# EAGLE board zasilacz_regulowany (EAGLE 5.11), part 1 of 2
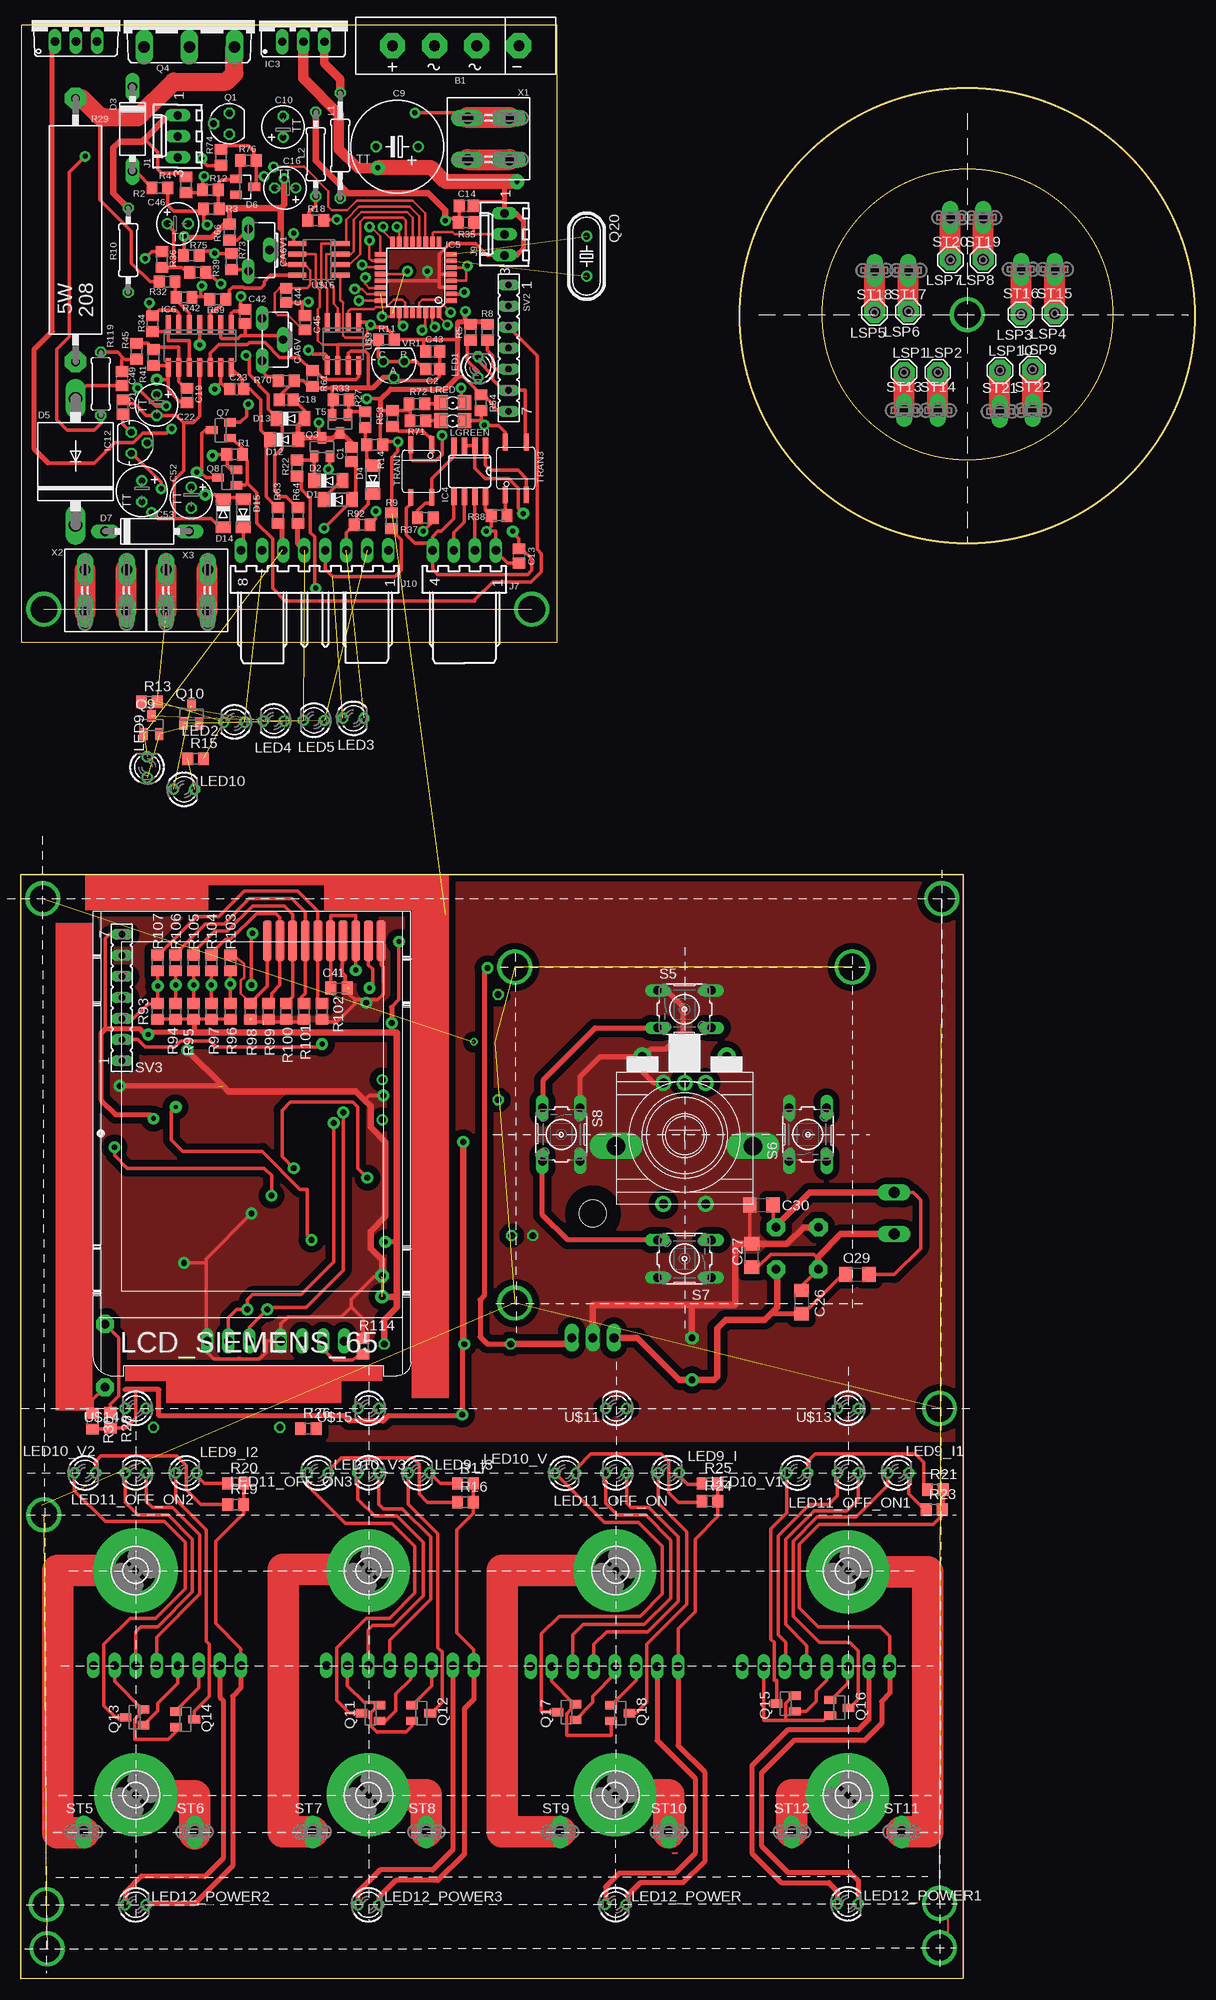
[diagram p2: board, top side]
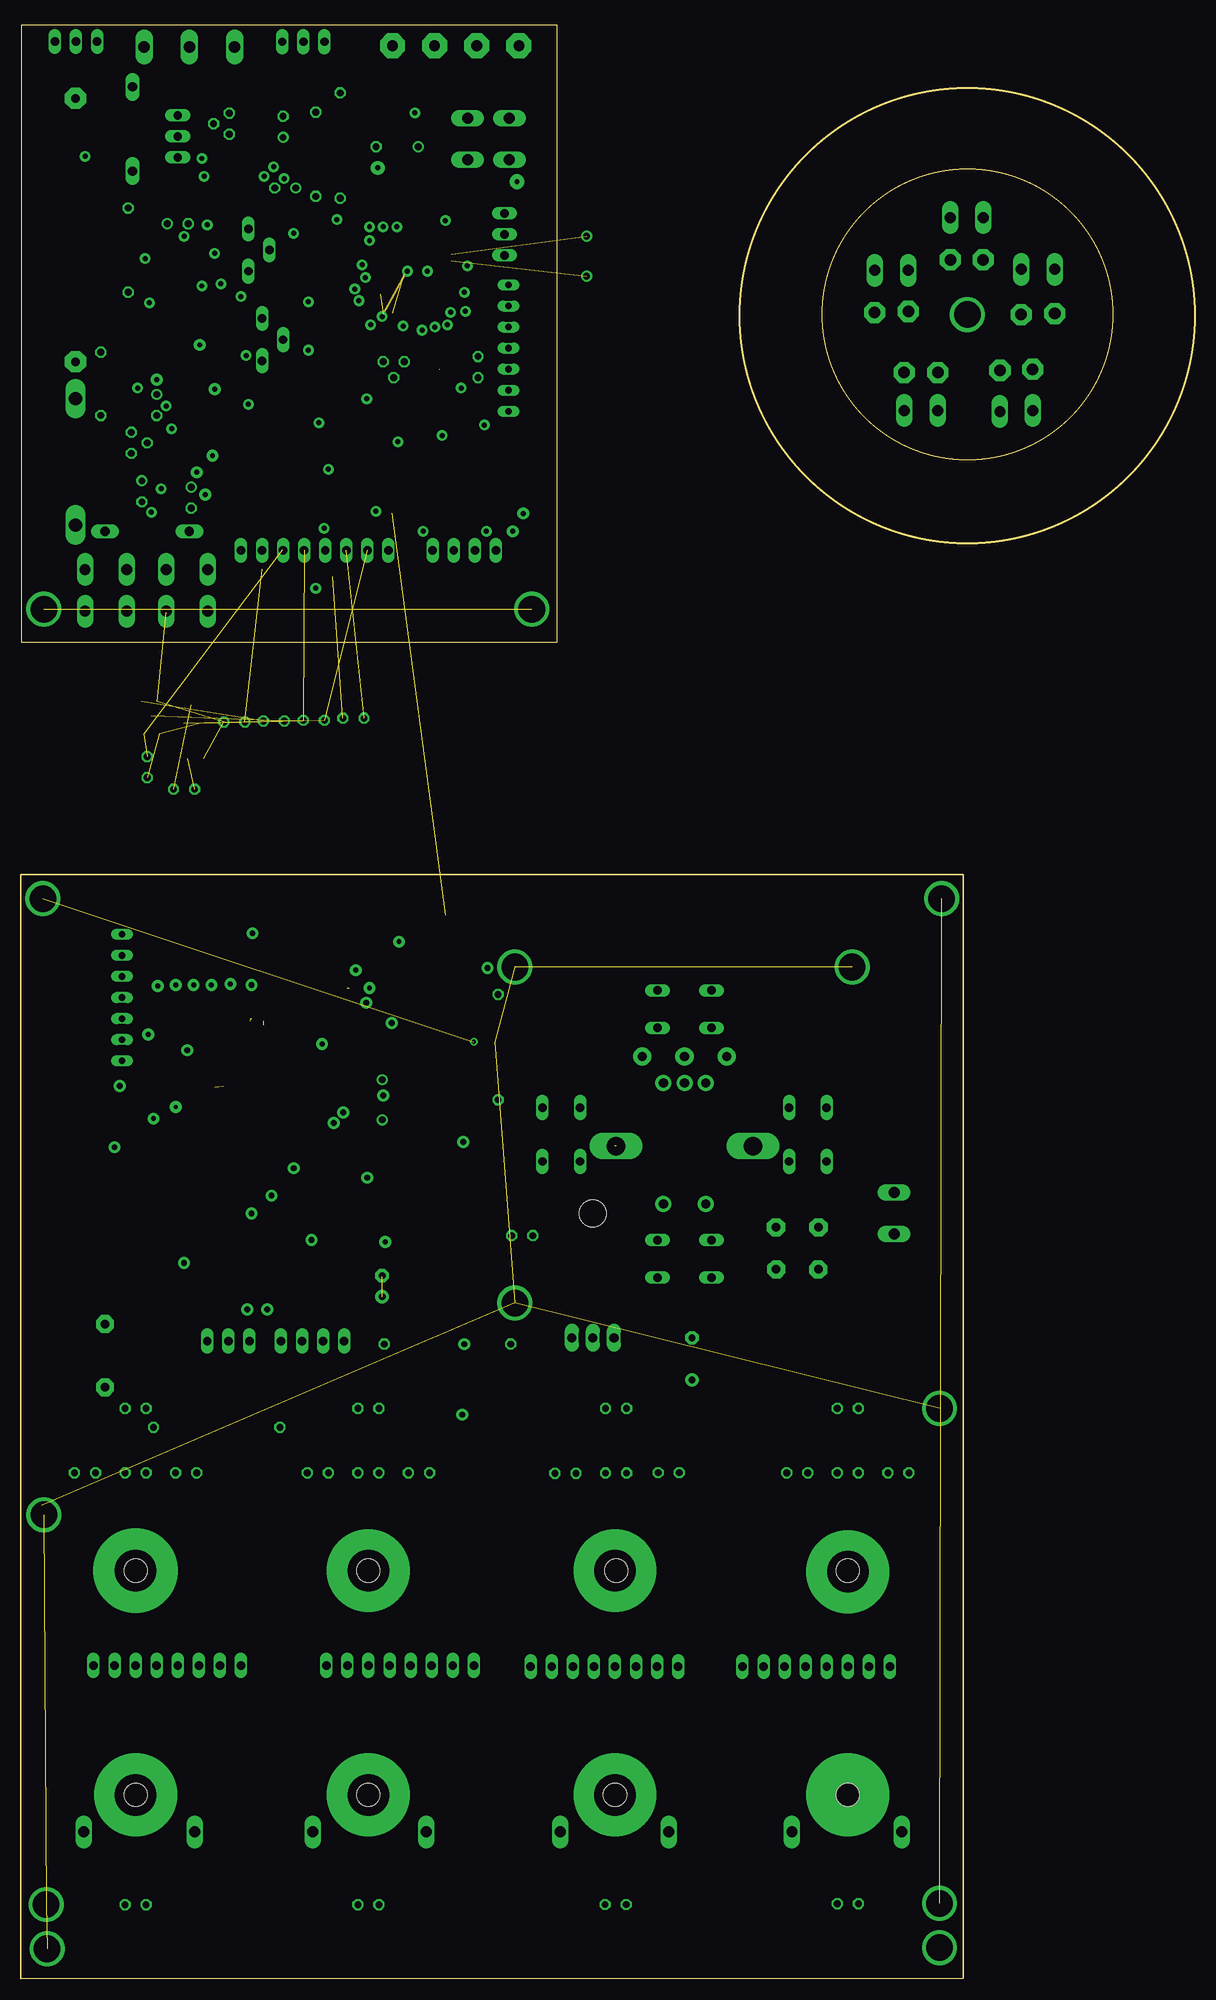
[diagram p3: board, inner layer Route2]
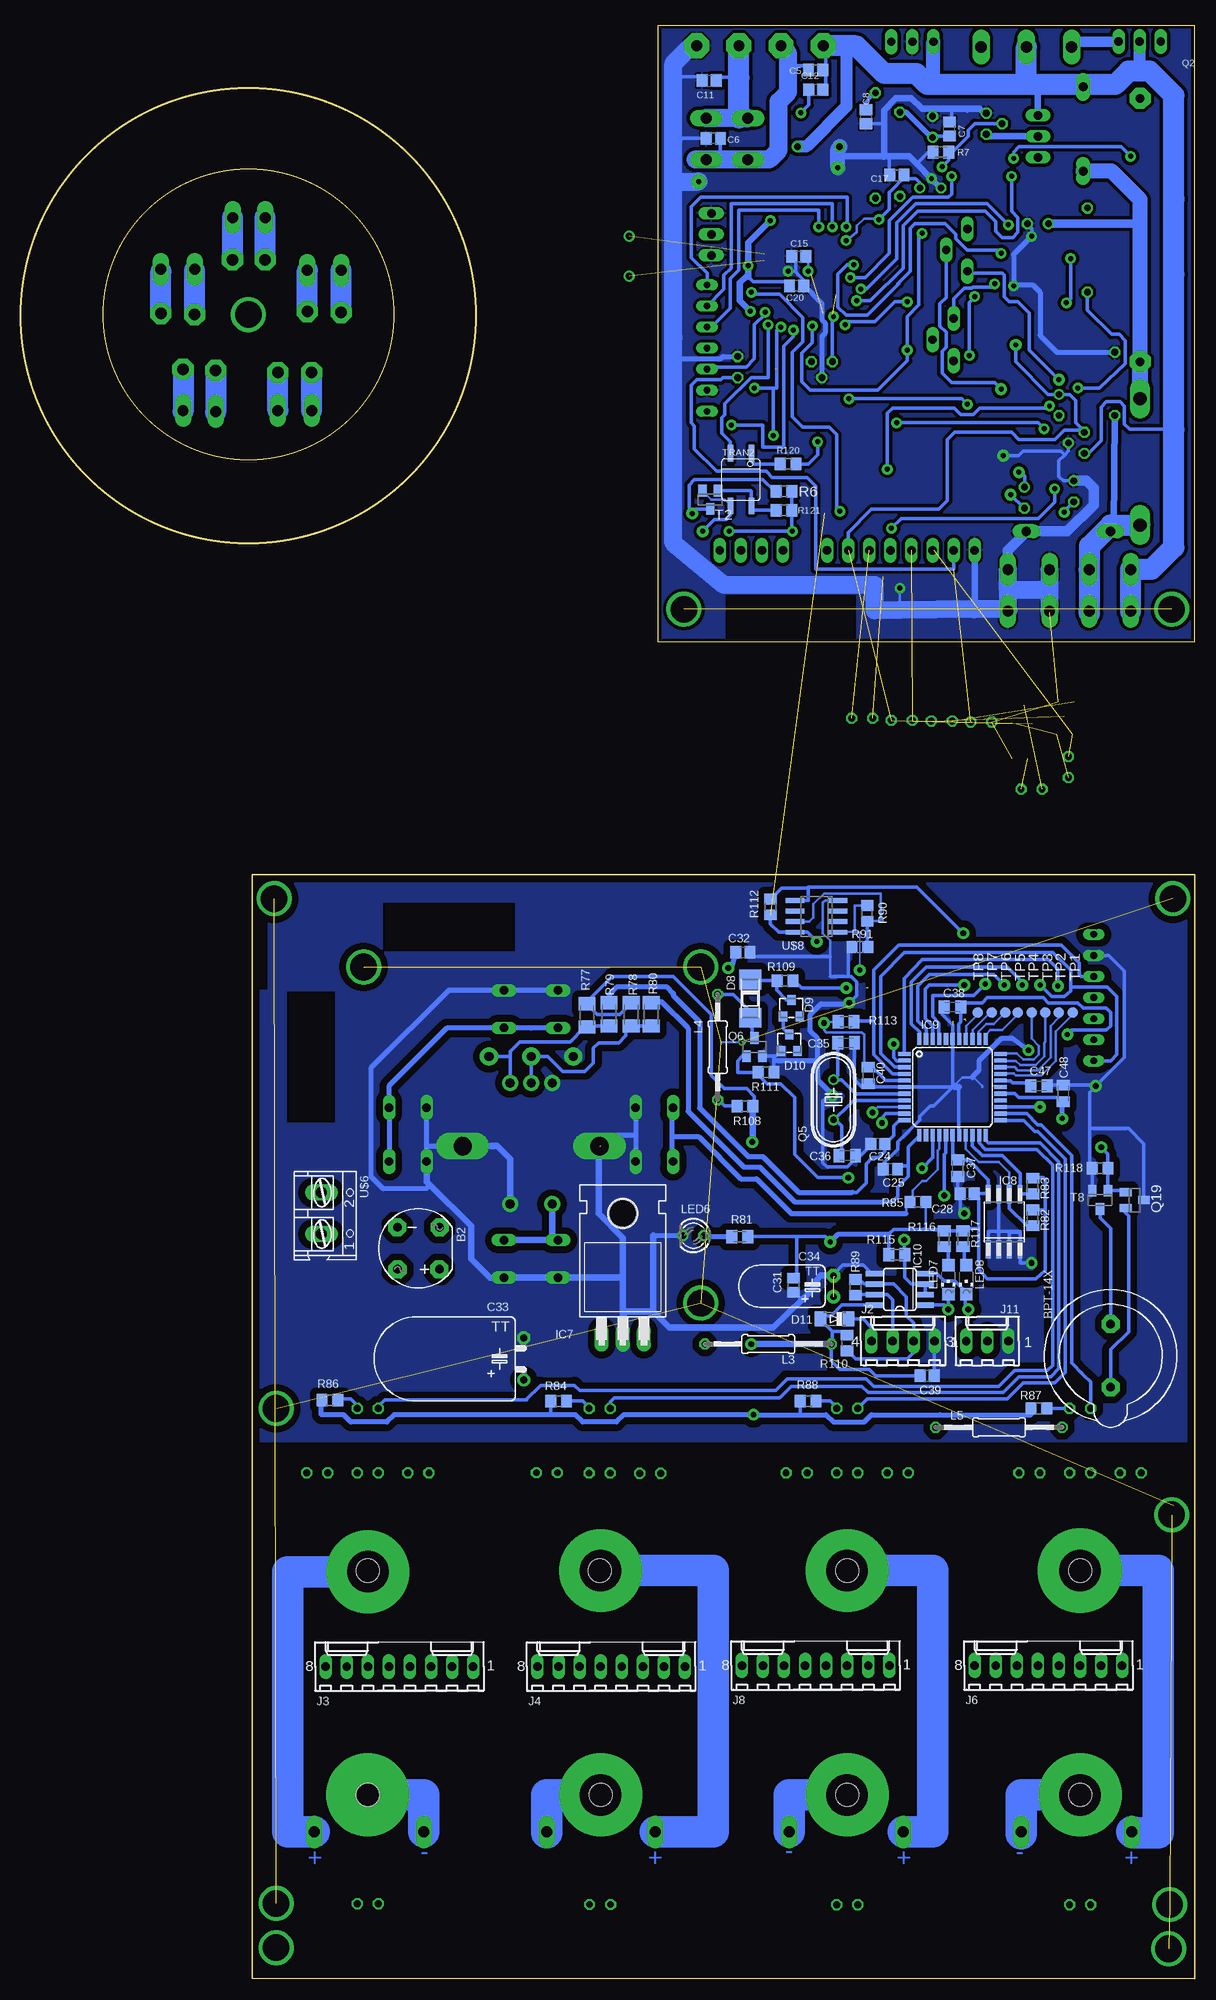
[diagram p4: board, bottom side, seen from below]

Size 141.52 x 235.56 mm. Coordinates in mm from the lower left corner, seen from the top.
Outline: 0.05,161.14 64.67,161.14 64.67,235.56 0.05,235.56 0.05,161.14
Outline: 0,0 113.61,0.05 113.61,133.12 0,133.15 0,0
Outline: circle at 114.09,200.65 radius 17.53
Outline: circle at 114.09,200.52 radius 27.43
Copper layers (1*16): Top 0.035mm / dielectric 1.5mm / Bottom 0.035mm
Design rules "default": minimum track width 10mil, minimum drill 20mil, track to track 8mil, track to pad 8mil, pad to pad 8mil, via to via 8mil, smd to smd 8mil, copper to edge 1mil, drill to drill 8mil, minimum pad ring 10mil, minimum via ring 8mil, stop-mask expansion 4mil, vias tented up to drill 0mil, thermal gap 10mil

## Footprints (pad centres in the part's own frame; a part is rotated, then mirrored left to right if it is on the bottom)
2KBB_R2 = drill 1.3 pad 3 octagon: + -7.62,0; - 7.62,0; ~1 -2.54,0; ~2 2.54,0
RB1A = drill 1.016 round: + -2.54,2.54 | drill 1.016 octagon: - 2.54,-2.54; AC1 2.54,2.54; AC2 -2.54,-2.54
F/HGP = drill 1.016 pad 2.159 octagon: 1 -3.81,0; 2 3.81,0
C0805 = smd 1.3 x 1.5: 1 -0.85,0; 2 0.85,0
TT5D11 = drill 0.813 round: + -2.54,0 | drill 0.813 octagon: - 2.54,0
TT2D5 = drill 0.813 round: + -1.27,0 | drill 0.813 octagon: - 1.27,0
C1206 = smd 1.6 x 1.8: 1 -1.4,0; 2 1.4,0
TT5D11L = drill 0.813 pad 1.6 round: + -2.54,0 | drill 0.813 pad 1.6 octagon: - 2.54,0
TT2D5L = drill 0.813 pad 1.6 round: + -1.27,0 | drill 0.813 pad 1.6 octagon: - 1.27,0
C0805K = smd 1.3 x 1.6: 1 -1,0; 2 1,0
TT2D6 = drill 0.813 round: + -1.27,0 | drill 0.813 octagon: - 1.27,0
CA6H = drill 1.016 long: A -2.54,0; E 2.54,0; S 0,2.54
MINIMELF = smd 1.4 x 1.8: A 1.7,0; C -1.7,0
P1-10 = drill 1.118 long: A 5.08,0; C -5.08,0
P6-15 = drill 1.6 long: A 7.62,0; C -7.62,0
SOT23 = smd 1 x 1.4: 1 -0.95,-1.1; 2 0.95,-1.1; 3 0,1.1
SOD106A = smd 2.4 x 2.6: A 2.3,0; K -2.3,0
TO236 = smd 1 x 1.2: A -1,-1; C 0,1; NC 1,-1
2,8 = hole 2.8: 0,0
78XXS = drill 1.016 long: GND 0,-2.54; IN -2.54,-2.54; OUT 2.54,-2.54
SO08 = smd 0.66 x 2.032: 1 -1.905,-3.073; 2 -0.635,-3.073; 3 0.635,-3.073; 4 1.905,-3.073; 5 1.905,3.073; 6 0.635,3.073; 7 -0.635,3.073; 8 -1.905,3.073
TQFP32-08 = smd 1.27 x 0.559: 1 -4.293,2.8; 2 -4.293,2; 3 -4.293,1.2; 4 -4.293,0.4; 5 -4.293,-0.4; 6 -4.293,-1.2; 7 -4.293,-2; 8 -4.293,-2.8; 17 4.293,-2.8; 18 4.293,-2; 19 4.293,-1.2; 20 4.293,-0.4; 21 4.293,0.4; 22 4.293,1.2; 23 4.293,2; 24 4.293,2.8 | smd 0.559 x 1.27: 9 -2.8,-4.293; 10 -2,-4.293; 11 -1.2,-4.293; 12 -0.4,-4.293; 13 0.4,-4.293; 14 1.2,-4.293; 15 2,-4.293; 16 2.8,-4.293; 25 2.8,4.293; 26 2,4.293; 27 1.2,4.293; 28 0.4,4.293; 29 -0.4,4.293; 30 -1.2,4.293; 31 -2,4.293; 32 -2.8,4.293
SO14 = smd 0.6 x 2.2: 1 -3.81,-2.6; 2 -2.54,-2.6; 3 -1.27,-2.6; 4 0,-2.6; 5 1.27,-2.6; 6 2.54,-2.6; 7 3.81,-2.6; 8 3.81,2.6; 9 2.54,2.6; 10 1.27,2.6; 11 0,2.6; 12 -1.27,2.6; 13 -2.54,2.6; 14 -3.81,2.6
TO220H = drill 1.118 long: 1 -2.54,-10.16; 2 0,-10.16; 3 2.54,-10.16 | hole 3.302: 0,4.826
SO-08M = smd 0.6 x 2.2: 1 -1.905,-3.33; 2 -0.635,-3.33; 3 0.635,-3.33; 4 1.905,-3.33; 5 1.905,3.33; 6 0.635,3.33; 7 -0.635,3.33; 8 -1.905,3.33
TQFP44 = smd 1.5 x 0.5: 1 -5.8,4; 2 -5.8,3.2; 3 -5.8,2.4; 4 -5.8,1.6; 5 -5.8,0.8; 6 -5.8,0; 7 -5.8,-0.8; 8 -5.8,-1.6; 9 -5.8,-2.4; 10 -5.8,-3.2; 11 -5.8,-4; 23 5.8,-4; 24 5.8,-3.2; 25 5.8,-2.4; 26 5.8,-1.6; 27 5.8,-0.8; 28 5.8,0; 29 5.8,0.8; 30 5.8,1.6; 31 5.8,2.4; 32 5.8,3.2; 33 5.8,4 | smd 0.5 x 1.5: 12 -4,-5.8; 13 -3.2,-5.8; 14 -2.4,-5.8; 15 -1.6,-5.8; 16 -0.8,-5.8; 17 0,-5.8; 18 0.8,-5.8; 19 1.6,-5.8; 20 2.4,-5.8; 21 3.2,-5.8; 22 4,-5.8; 34 4,5.8; 35 3.2,5.8; 36 2.4,5.8; 37 1.6,5.8; 38 0.8,5.8; 39 0,5.8; 40 -0.8,5.8; 41 -1.6,5.8; 42 -2.4,5.8; 43 -3.2,5.8; 44 -4,5.8
78LXX = drill 0.813 octagon: GND 0,1.905; IN 1.27,0; OUT -1.27,0
6410-03 = drill 1.016 long: 1 2.54,0; 2 0,0; 3 -2.54,0
6410-04 = drill 1.016 long: 1 3.81,0; 2 1.27,0; 3 -1.27,0; 4 -3.81,0
6410-08 = drill 1.016 long: 1 8.89,0; 2 6.35,0; 3 3.81,0; 4 1.27,0; 5 -1.27,0; 6 -3.81,0; 7 -6.35,0; 8 -8.89,0
7395-04 = drill 1.016 long: 1 3.81,0; 2 1.27,0; 3 -1.27,0; 4 -3.81,0
7395-08 = drill 1.016 long: 1 8.89,0; 2 6.35,0; 3 3.81,0; 4 1.27,0; 5 -1.27,0; 6 -3.81,0; 7 -6.35,0; 8 -8.89,0
0207/12 = drill 0.813 octagon: 1 -6.35,0; 2 6.35,0
0207/10 = drill 0.813 octagon: 1 -5.08,0; 2 5.08,0
0207/15@1 = drill 0.813 octagon: 1 -7.62,0; 2 7.62,0
LED3MM = drill 0.813 octagon: A -1.27,0; K 1.27,0
CHIPLED_1206 = smd 1.5 x 1.5: A 0,-1.75; C 0,1.75
1206 = smd 1.6 x 1.803: A -1.422,0; C 1.422,0
SE14 = drill 1.397 pad 2.54 octagon: MP 0,0
SOT54E = drill 0.813 octagon: D -1.27,0; G 0,1.905; S 1.27,0
TO220AV = drill 1.016 long: B -2.54,-2.54; C 0,-2.54; E 2.54,-2.54
TOP3AV = drill 1.397 long: B -5.461,-3.175; C 0,-3.175; E 5.461,-3.175
HC49U70 = drill 0.813 round: 1 -2.413,0; 2 2.413,0
HC49/S = drill 0.813 round: 1 -2.413,0; 2 2.413,0
R0805 = smd 1.3 x 1.5: 1 -0.95,0; 2 0.95,0
M0805 = smd 1.3 x 1.6: 1 -0.95,0; 2 0.95,0
KH208-8 = drill 1.016 pad 2.54 octagon: 1 -15.875,0; 2 15.875,0
M1206 = smd 1.6 x 2: 1 -1.4,0; 2 1.4,0
0207/7 = drill 0.813 octagon: 1 -3.81,0; 2 3.81,0
B3F-10XX = drill 1.016 long: 1 -3.251,2.261; 2 3.251,2.261; 3 -3.251,-2.261; 4 3.251,-2.261
ST2,8 = drill 1.321 long: 1 0,0
FE07 = drill 0.813 long: 1 -7.62,0; 2 -5.08,0; 3 -2.54,0; 4 0,0; 5 2.54,0; 6 5.08,0; 7 7.62,0
B1,27 = smd 1.27 x 1.27: PP 0,0
MFP4 = smd 2.032 x 0.635: 1 -3.226,1.295; 2 -3.226,-1.245; 3 3.15,-1.245; 4 3.15,1.295
ENKODER_PROSTY = drill 1.1 pad 2.184 round: A -5.08,0; B 0,0; C 5.08,0 | drill 1.1 pad 1.93 round: A.A -2.54,3.175; B.B 0,3.175; C.C 2.54,3.175; S1 -2.54,17.78; S2 2.54,17.78 | drill 2.2 pad 3 long: GN -8.255,10.795; GN1 8.255,10.795
AK300/2_MK = drill 1.321 long: 1 -2.515,0; 2 2.489,0
SIEMENS65 = smd 5 x 1.1: 1V8 -21.463,11.938; 2V9 -21.463,8.89; CLK -21.463,5.842; CS -21.463,4.318; DAT -21.463,7.366; GND -21.463,10.414; LED+ -21.463,13.462; LED_GND -21.463,14.986; RESET -21.463,2.794; RS -21.463,1.27
SO08' = smd 0.6 x 2.2: 1 -1.905,-2.6; 2 -0.635,-2.6; 3 0.635,-2.6; 4 1.905,-2.6; 5 1.905,2.6; 6 0.635,2.6; 7 -0.635,2.6; 8 -1.905,2.6
SO-08 = smd 0.6 x 2.2: 1 -1.905,-2.6; 2 -0.635,-2.6; 3 0.635,-2.6; 4 1.905,-2.6; 5 1.905,2.6; 6 0.635,2.6; 7 -0.635,2.6; 8 -1.905,2.6
TO92-CLP = drill 0.813 octagon: A 0,1.905; C 1.27,0; R -1.27,0
SH5-2 = drill 1.321 long: 1 0,-2.515; 2 0,2.515; 3 5.004,-2.515; 4 5.004,2.515

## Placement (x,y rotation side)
B1  B600C8000  [2KBB_R2]  52.42,233.06 0 top
B2  B50C1500  [RB1A]  93.59,88.07 180 bottom
BPT-14X  BPT-14X  [F/HGP]  10.15,75.12 90 bottom
C1  10n  [C0805]  39.87,183.78 270 top
C2  1n  [C0805]  49.65,194.07 0 top
C5  100n  [C0805]  45.72,230.13 0 bottom
C6  100n  [C0805]  58.03,221.88 180 bottom
C7  100n  [C0805]  29.59,223.02 90 bottom
C8  100n  [C0805]  39.64,224.5 270 bottom
C9  1000u/25V  [TT5D11]  45.36,220.89 180 top
C10  100u  [TT2D5]  31.62,223.28 90 top
C11  100n  [C0805]  58.54,228.87 0 bottom
C12  100n  [C0805]  45.69,227.75 0 bottom
C13  100n  [C0805]  60.04,171.54 270 top
C14  100n  [C0805]  53.69,213.75 0 top
C15  1n  [C0805]  47.75,207.66 0 bottom
C16  4u7  [TT2D5]  31.87,215.91 180 top
C17  100n  [C0805]  35.91,217.46 0 bottom
C18  10n  [C0805]  32,190.38 180 top
C19  10n  [C0805]  20.06,190.89 90 top
C20  100n  [C0805]  48,204.1 180 bottom
C21  100n  [C0805]  12.31,189.5 90 top
C22  10u  [TT2D5]  16.38,189.75 270 top
C23  10n  [C0805]  26.03,191.65 0 top
C24  1n  [C0805]  38.22,100.65 180 bottom
C25  1n  [C0805]  36.7,97.6 180 bottom
C26  100n  [C1206]  94.1,81.6 270 top
C27  100n  [C1206]  88.13,87.21 90 top
C28  100n  [C0805]  27.43,94.68 180 bottom
C29  100n  [C1206]  100.83,84.9 0 top
C30  100n  [C1206]  89.28,93.28 0 top
C31  100n  [C0805]  48.38,83.63 270 bottom
C32  100n  [C0805]  54.48,123.76 0 bottom
C33  1000u/25V  [TT5D11L]  80.89,74.74 90 bottom
C34  100u  [TT2D5L]  43.56,83.5 90 bottom
C35  15p  [C0805K]  42.03,112.84 180 bottom
C36  15p  [C0805K]  41.91,99.25 180 bottom
C37  100n  [C0805K]  28.57,97.72 270 bottom
C38  100n  [C0805K]  29.2,117.16 0 bottom
C39  100n  [C0805]  32.25,72.71 180 bottom
C40  100n  [C0805K]  39.36,108.9 90 bottom
C41  100n  [C0805K]  38.35,119.44 180 top
C42  10n  [C0805]  27.05,200.42 270 top
C43  100n  [C0805]  49.65,196.23 0 top
C44  100n  [C0805]  32,202.96 270 top
C45  100n  [C0805]  34.28,199.65 270 top
C46  1u  [TT2D5]  18.92,211.59 0 top
C47  1n5  [C0805K]  18.79,107.63 0 bottom
C48  100n  [C0805K]  15.87,106.74 270 bottom
C49  100n  [C0805]  12.19,192.92 270 top
C52  22u  [TT2D5]  20.54,178.57 270 top
C53  100u  [TT2D6]  14.6,179.33 270 top
CA6V  1k  [CA6H]  29.08,197.62 270 top
CA6V1  1k  [CA6H]  27.43,208.42 270 top
D1  BAV103  [MINIMELF]  38.22,178.32 0 top
D2  BAV103  [MINIMELF]  37.08,180.6 0 top
D3  1N4002  [P1-10]  13.46,223.02 270 top
D4  [MINIMELF]  42.41,180.73 90 top
D5  BY550  [P6-15]  6.6,182.89 90 top
D6  5v6  [SOT23]  27.05,216.04 270 top
D7  1N4002  [P1-10]  15.23,174.51 0 top
D8  BYS10-45  [SOD106A]  53.59,118.17 270 bottom
D9  6v2  [TO236]  48.64,117.03 0 bottom
D10  6v2  [TO236]  48.89,112.84 0 bottom
D11  BAV103  [MINIMELF]  43.43,79.56 180 bottom
D12  BAS85  [MINIMELF]  31.74,185.56 0 top
D13  BAS85  [MINIMELF]  32.51,188.1 0 top
D14  BAS85  [MINIMELF]  24.38,176.67 270 top
D15  BAS85  [MINIMELF]  26.79,176.67 90 top
H1  MOUNT-HOLE2.8  [2,8]  13.84,22.16 0 top
H2  MOUNT-HOLE2.8  [2,8]  13.84,49.21 0 top
H3  MOUNT-HOLE2.8  [2,8]  41.91,49.21 0 top
H4  MOUNT-HOLE2.8  [2,8]  41.91,22.16 0 top
H5  MOUNT-HOLE2.8  [2,8]  71.62,22.16 0 top
H6  MOUNT-HOLE2.8  [2,8]  71.75,49.21 0 top
H7  MOUNT-HOLE2.8  [2,8]  99.69,49.21 0 top
H8  MOUNT-HOLE2.8  [2,8]  99.69,22.16 0 top
IC3  7805/T0220  [78XXS]  34.06,236.08 0 top
IC4  SN75176  [SO08]  54.1,181.75 180 top
IC5  ATMEGA8-16AU  [TQFP32-08]  47.62,205.12 180 top
IC6  TL084-SMD  [SO14]  21.58,196.86 180 top
IC7  7805T  [TO220H]  68.96,87.44 0 bottom
IC8  24C16SM  [SO-08M]  22.98,91.25 0 bottom
IC9  ATMEGA32-16AU  [TQFP44]  29.2,107.5 0 bottom
IC10  SN75176  [SO08]  35.55,83.12 90 bottom
IC12  78L24  [78LXX]  13.33,185.18 270 top
J1  zlacze NS25-W3P  [6410-03]  18.92,222.13 90 top
J2  zlacze NS25-W4P  [6410-04]  35.17,76.9 0 bottom
J3  zlacze NS25-W8K  [6410-08]  95.88,37.65 0 bottom
J4  zlacze NS25-W8K  [6410-08]  70.35,37.65 0 bottom
J6  zlacze NS25-W8K  [6410-08]  17.65,37.78 0 bottom
J7  zlacze NS25-W4K  [7395-04]  53.46,172.22 0 top
J8  zlacze NS25-W8K  [6410-08]  45.72,37.78 0 bottom
J9  zlacze NS25-W3P  [6410-03]  58.29,210.32 90 top
J10  zlacze NS25-W8K  [7395-08]  35.43,172.22 0 top
J11  zlacze NS25-W3P  [6410-03]  25.01,76.9 0 bottom
L1  1u/osiowy  [0207/12]  38.5,221.02 90 top
L2  100u/osiowy  [0207/10]  35.55,219.97 270 top
L3  1u  [0207/15@1]  51.43,76.52 180 bottom
L4  220u  [0207/12]  57.53,112.33 90 bottom
L5  1u  [0207/15@1]  23.62,66.48 180 bottom
LED1  [LED3MM]  55.11,194.32 90 top
LED2  [LED3MM]  25.75,151.52 180 top
LED3  [LED3MM]  40.1,151.98 0 top
LED4  RED  [LED3MM]  30.5,151.65 180 top
LED5  RED  [LED3MM]  35.33,151.73 180 top
LED6  LED3mm  [LED3MM]  60.45,89.6 180 bottom
LED7  1206  [CHIPLED_1206]  29.71,84.26 180 bottom
LED8  1206  [CHIPLED_1206]  27.55,84.26 180 bottom
LED9  RED  [LED3MM]  15.23,146.09 90 top
LED9_I  [LED3MM]  78.1,61.02 0 top
LED9_I1  [LED3MM]  105.79,61 0 top
LED9_I2  [LED3MM]  19.93,61 0 top
LED9_I3  [LED3MM]  48,61 0 top
LED10  RED  [LED3MM]  19.68,143.42 0 top
LED10_V  [LED3MM]  65.65,60.95 0 top
LED10_V1  [LED3MM]  93.59,61 0 top
LED10_V2  [LED3MM]  7.74,61 0 top
LED10_V3  [LED3MM]  35.81,61 0 top
LED11_OFF_ON  [LED3MM]  71.75,60.97 180 top
LED11_OFF_ON1  [LED3MM]  99.69,61 180 top
LED11_OFF_ON2  [LED3MM]  13.84,61 180 top
LED11_OFF_ON3  [LED3MM]  41.91,61 180 top
LED12_POWER  [LED3MM]  71.7,8.95 0 top
LED12_POWER1  [LED3MM]  99.69,9.05 0 top
LED12_POWER2  [LED3MM]  13.84,8.93 0 top
LED12_POWER3  [LED3MM]  41.91,8.93 0 top
LGREEN  1206  [1206]  52.06,187.84 0 top
LRED  1206  [1206]  52.06,190 0 top
LSP1  SE14  [SE14]  106.47,193.66 0 top
LSP2  SE14  [SE14]  110.54,193.66 0 top
LSP3  SE14  [SE14]  120.57,200.65 180 top
LSP4  SE14  [SE14]  124.63,200.77 180 top
LSP5  SE14  [SE14]  102.92,200.9 180 top
LSP6  SE14  [SE14]  106.98,201.03 180 top
LSP7  SE14  [SE14]  112.06,207.25 180 top
LSP8  SE14  [SE14]  116,207.25 180 top
LSP9  SE14  [SE14]  121.97,194.04 0 top
LSP10  SE14  [SE14]  118.03,193.91 0 top
Q1  BS170  [SOT54E]  25.14,223.66 90 top
Q2  BD243  [TO220AV]  6.65,236.1 0 top
Q3  BCW67C  [SOT23]  36.32,184.67 0 top
Q4  BD245  [TOP3AV]  20.31,236.1 0 top
Q5  16MHz  [HC49U70]  43.56,105.98 90 bottom
Q6  BSS123  [SOT23]  53.08,112.33 0 bottom
Q7  BSS84  [SOT23]  24.12,186.7 90 top
Q8  BSS123  [SOT23]  24.89,180.99 90 top
Q9  BSS84  [SOT23]  15.74,151.17 0 top
Q10  BSS84  [SOT23]  20.57,152.44 0 top
Q11  BSS84  [SOT23]  42.16,32.04 90 top
Q12  BSS84  [SOT23]  48.25,32.04 270 top
Q13  BSS84  [SOT23]  13.71,31.53 90 top
Q14  BSS84  [SOT23]  19.81,31.28 270 top
Q15  BSS84  [SOT23]  92.2,33.18 90 top
Q16  BSS84  [SOT23]  98.67,32.68 270 top
Q17  BSS84  [SOT23]  65.78,32.17 90 top
Q18  BSS84  [SOT23]  72.26,32.04 270 top
Q19  BSS84  [SOT23]  7.23,93.89 270 bottom
Q20  [HC49/S]  68.19,207.68 270 top
R1  100k  [R0805]  25.78,183.78 180 top
R2  4k7  [R0805]  16.76,215.91 180 top
R3  560  [R0805]  22.98,213.37 180 top
R4  4k7  [R0805]  19.93,216.29 270 top
R5  470  [R0805]  54.22,198.51 270 top
R6  1k  [R0805]  49.52,179.33 180 bottom
R7  100k  [M0805]  30.6,220.23 180 bottom
R8  10k  [R0805]  56.26,198.51 90 top
R9  1k  [R0805]  44.7,175.78 90 top
R10  56  [0207/10]  12.95,208.42 90 top
R11  470  [R0805]  44.06,197.62 0 top
R12  330  [R0805]  22.85,215.66 0 top
R13  4k7  [R0805]  15.49,153.96 0 top
R14  1k  [R0805]  42.67,184.92 0 top
R15  k47  [R0805]  21.08,147.1 0 top
R16  10k  [R0805]  53.59,57.44 0 top
R17  4k7  [R0805]  53.59,59.73 0 top
R18  1R5  [R0805]  35.55,211.97 0 top
R19  4k7  [R0805]  25.9,57.19 0 top
R20  4k7  [R0805]  25.9,59.73 0 top
R21  4k7  [R0805]  110.23,58.96 0 top
R22  10k  [R0805]  33.27,182.13 270 top
R23  4k7  [R0805]  110.1,56.55 0 top
R24  4k7  [R0805]  83.05,57.57 0 top
R25  4k7  [R0805]  83.05,59.73 0 top
R26  300  [R0805]  34.67,66.33 0 top
R27  2k2  [R0805]  41.52,187.97 270 top
R28  1k  [R0805]  10.79,67.35 270 top
R29  0.56/5W  [KH208-8]  6.6,210.83 270 top
R30  1k  [R0805]  8.63,67.22 270 top
R32  3k3/1%  [R0805]  17.65,204.61 180 top
R33  1k  [R0805]  38.6,190.38 0 top
R34  1k5/1%  [R0805]  15.87,199.53 270 top
R35  4k7  [R0805]  53.67,211.77 180 top
R36  3k3/1%  [R0805]  17.01,207.27 90 top
R37  1k  [R0805]  48.76,176.16 180 top
R38  330  [M0805]  57.65,176.41 0 top
R39  10k  [R0805]  21.33,205.75 180 top
R41  3k9/1%  [R0805]  16,195.46 90 top
R42  1k5/1%  [R0805]  19.68,202.7 180 top
R45  1k5/1%  [R0805]  13.96,196.23 270 top
R53  330  [R0805]  44.83,188.1 270 top
R54  1k  [R0805]  55.49,190 270 top
R61  4k7  [R0805]  35.17,192.92 90 top
R63  10k  [R0805]  30.98,176.41 90 top
R64  10k  [R0805]  33.4,176.41 90 top
R66  3k9  [R0805]  25.14,210.58 90 top
R69  4k7  [R0805]  23.74,202.45 0 top
R70  1k  [R0805]  32,192.67 180 top
R71  470  [R0805]  47.87,187.84 0 top
R72  470  [R0805]  47.75,189.88 0 top
R73  1k5  [R0805]  25.39,207.02 90 top
R74  4k7  [R0805]  24.12,219.59 270 top
R75  5k6  [R0805]  20.57,207.78 0 top
R76  560  [R0805]  27.43,219.21 0 top
R77  10k  [M1206]  73.27,116.14 270 bottom
R78  10k  [M1206]  67.94,116.27 90 bottom
R79  1  [M1206]  70.61,116.27 90 bottom
R80  1  [M1206]  65.53,116.27 90 bottom
R81  680  [M0805]  54.86,89.47 180 bottom
R82  4k7  [M0805]  19.55,91.76 270 bottom
R83  4k7  [M0805]  19.55,95.57 270 bottom
R84  680  [R0805]  76.7,69.66 0 bottom
R85  4k7  [R0805]  33.4,93.66 180 bottom
R86  680  [R0805]  104.26,69.78 0 bottom
R87  680  [R0805]  18.79,68.77 0 bottom
R88  680  [R0805]  46.6,69.66 0 bottom
R89  120  [R0805]  40.89,83.37 90 bottom
R90  470  [R0805]  39.49,128.46 90 bottom
R91  330  [R0805]  40.38,124.39 0 bottom
R92  100  [R0805]  41.14,175.27 180 top
R93  4k7  [R0805]  16.5,116.65 270 top
R94  4k7  [R0805]  18.66,116.65 270 top
R95  4k7  [R0805]  20.82,116.65 270 top
R96  4k7  [R0805]  25.27,116.65 270 top
R97  4k7  [R0805]  22.98,116.65 270 top
R98  470  [R0805]  27.68,116.65 270 top
R99  470  [R0805]  29.84,116.65 270 top
R100  470  [R0805]  32,116.65 270 top
R101  470  [R0805]  34.16,116.65 270 top
R102  470  [R0805]  36.32,116.65 270 top
R103  330  [R0805]  25.27,122.49 270 top
R104  330  [R0805]  22.98,122.49 270 top
R105  330  [R0805]  20.82,122.49 270 top
R106  330  [R0805]  18.66,122.49 270 top
R107  330  [R0805]  16.5,122.49 270 top
R108  1  [R0805]  54.22,105.22 180 bottom
R109  1  [R0805]  49.4,120.33 0 bottom
R110  510  [R0805]  41.91,76.64 90 bottom
R111  1k  [R0805]  51.68,109.28 0 bottom
R112  100k  [R0805]  51.18,129.22 270 bottom
R113  10k  [M0805]  42.03,115.38 180 bottom
R114  510  [R0805]  41.27,76.26 270 top
R115  4k7  [M0805]  35.94,87.31 180 bottom
R116  680  [M0805]  30.22,89.22 270 bottom
R117  680  [M0805]  27.93,89.22 270 bottom
R118  47k  [R0805]  11.42,97.72 0 bottom
R119  1k5  [0207/7]  9.65,192.29 270 top
R120  330  [R0805]  49.02,182.64 180 bottom
R121  10k  [R0805]  49.52,177.05 180 bottom
S5  [B3F-10XX]  80,116.9 0 top
S6  [B3F-10XX]  94.86,101.79 90 top
S7  [B3F-10XX]  80,86.8 180 top
S8  [B3F-10XX]  65.15,101.79 270 top
ST5  [ST2,8]  7.61,17.71 0 top
ST6  [ST2,8]  20.95,17.71 0 top
ST7  [ST2,8]  35.17,17.71 0 top
ST8  [ST2,8]  48.89,17.71 0 top
ST9  [ST2,8]  65.02,17.71 0 top
ST10  [ST2,8]  78.1,17.71 0 top
ST11  [ST2,8]  106.17,17.71 0 top
ST12  [ST2,8]  92.96,17.71 0 top
ST13  [ST2,8]  106.47,189.09 0 top
ST14  [ST2,8]  110.54,189.09 0 top
ST15  [ST2,8]  124.63,206.11 180 top
ST16  [ST2,8]  120.57,206.11 180 top
ST17  [ST2,8]  106.98,205.98 180 top
ST18  [ST2,8]  102.92,205.98 180 top
ST19  [ST2,8]  116,212.33 180 top
ST20  [ST2,8]  112.06,212.33 180 top
ST21  [ST2,8]  118.03,188.96 0 top
ST22  [ST2,8]  121.97,189.09 0 top
SV2  [FE07]  58.8,196.61 270 top
SV3  [FE07]  12.19,118.3 90 top
T2  BC847  [SOT23]  58.41,178.32 180 bottom
T5  BCX41  [SOT23]  38.48,187.46 180 top
T8  BSS123  [SOT23]  11.42,93.91 180 bottom
TP1  PTR1B1,27  [B1,27]  14.73,116.52 0 bottom
TP2  PTR1B1,27  [B1,27]  16.38,116.52 0 bottom
TP3  PTR1B1,27  [B1,27]  18.03,116.52 0 bottom
TP4  PTR1B1,27  [B1,27]  19.68,116.52 0 bottom
TP5  PTR1B1,27  [B1,27]  21.33,116.52 0 bottom
TP6  PTR1B1,27  [B1,27]  22.85,116.52 0 bottom
TP7  PTR1B1,27  [B1,27]  24.51,116.52 0 bottom
TP8  PTR1B1,27  [B1,27]  26.16,116.52 0 bottom
TRAN1  PC357Z  [MFP4]  48.25,181.75 270 top
TRAN2  PC357Z  [MFP4]  54.73,180.73 270 bottom
TRAN3  PC357Z  [MFP4]  59.68,182.13 90 top
U$5  ED16112O  [ENKODER_PROSTY]  80,111.19 180 top
U$6  TB-5.0-P-2P/BL  [AK300/2_MK]  105.28,92.26 270 bottom
U$7  SIEMENS_65/model LS0..  [SIEMENS65]  28.44,103.69 270 top
U$8  LP2951CM-3.0  [SO08']  45.59,128.08 90 bottom
U$9  MCP4921  [SO-08]  38.86,197.11 180 top
U$11  [LED3MM]  71.75,68.77 180 top
U$13  [LED3MM]  99.69,68.77 180 top
U$14  [LED3MM]  13.84,68.77 180 top
U$15  [LED3MM]  41.91,68.77 180 top
U$16  MCP4921  [SO-08]  35.94,207.27 90 top
VR1  TL431/TO92  [TO92-CLP]  44.95,194.96 180 top
X1  zlacze LST1407  [SH5-2]  56.38,219.34 90 top
X2  zlacze LST1407  [SH5-2]  7.74,167.4 0 top
X3  zlacze LST1407  [SH5-2]  17.52,167.4 0 top

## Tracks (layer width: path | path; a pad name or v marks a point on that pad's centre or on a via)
0V  (via drill 0.7 pad 1.42)  (7 unrouted)
  Top 0.152: 27.68,115.45 27.6,115.45 27.6,115.5 29.2,115.5
  Top 0.406: 40.25,118.04 39.62,118.68 39.62,119.44 39.11,119.95 39.11,120.97 38.73,121.35 38.73,124.78 38.98,125.03 U$7.GND | 41.65,118.04 40.25,118.04 | 41.65,118.04 43.05,118.04 43.68,118.68 43.68,121.98 43.43,122.24 U$7.LED_GND | 27.87,115.7 28.19,115.38 29.71,115.38 29.84,115.5 R99.2 30.03,115.7 30.35,115.38 31.74,115.38 32,115.63 R100.2 32.19,115.7 32.51,115.38 33.9,115.38 34.16,115.63 R101.2 34.35,115.7 34.67,115.38 | R102.2 36.32,115.63 36.06,115.38 38.09,115.38 40.25,117.54 40.25,118.04 | v41.65,117.66 41.65,118.04 | 39.81,81.02 38.6,79.82 32.25,79.82 31.36,78.93 J2.1 29.59,76.9 29.59,75.5 28.82,74.74 23.24,74.74 22.47,75.5 J11.1 22.35,77.02 22.35,86.29 | v27.81,92.26 22.35,86.8 22.35,86.29 | 22.35,86.29 v19.68,86.29 | 87.19,88.61 C27.2 87.88,88.86 C30.1 | R114.1 41.27,79.56 39.81,81.02 | 43.3,84.64 43.43,84.77 C34.- 43.43,84.64 42.54,84.64 39.81,81.91 39.81,81.02 | 43.68,84.77 43.56,84.64 | 43.43,106.49 42.03,106.49 41.46,105.92
  Top 0.61: 43.43,106.49 v43.68,106.49 | 24.38,107.63 v11.93,107.63 | S8.1 67.41,105.07 67.43,105.09 67.43,108.77 69.84,111.19 U$5.C | S5.1 77.87,119.16 79.88,117.16 79.88,114.23 77.72,112.08 75.94,112.08 75.05,111.19 U$5.C | U$5.C.C 76.32,108.01 74.92,109.41 U$5.C
  Top 0.813: IC7.2 68.96,81.21 80.89,81.21 | 80.89,81.21 86.1,81.21 86.1,88.2 86.48,88.58 86.99,88.58 | v20.06,111.95 24.38,107.63 25.01,107 40.38,107 41.46,105.92 42.16,105.22 42.16,102.68 43.94,100.9 43.94,91.88 42.16,90.1 42.16,88.07 43.56,86.68 C34.- | 86.99,88.58 92.32,88.58 94.36,90.61 B2.- | 86.99,88.58 87.02,88.61 87.19,88.61 | 80.89,81.21 C33.-
  Bottom 0.305: 25.65,107.5 25.65,107.63 26.66,108.65 26.79,108.65 28.06,108.65 29.08,107.63 | U$8.4 44.57,129.98 44.83,129.73 44.83,126.05 43.94,125.16 43.94,123.25 43.94,120.84 | D10.A 50.67,111.06 50.67,110.68
  Bottom 0.406: 29.2,107.5 IC9.39 29.2,115 30.47,116.27 30.47,116.65 30.2,116.92 C38.1 | IC9.28 23.36,107.5 | 29.2,107.5 28.44,107.5 28.44,101.7 IC9.18 | 29.2,107.5 IC9.6 39.87,107.5 | 50.8,111.23 50.5,111.23 D10.A | 50.8,111.23 Q6.2 | 50.8,111.23 50.8,111.06 50.73,111 R111.2 | v41.65,117.66 40.76,118.55 40.76,120.2 41.4,120.84 41.78,120.84 | T8.2 12.37,95.12 12.31,95.18 12.37,95.25 R118.1 12.69,97.72 12.69,102.53 | 24.89,87.82 IC8.1 24.89,90.1 23.62,90.1 | 21.08,89.98 IC8.4 | 21.08,89.98 21.08,90.1 22.35,90.1 | 22.35,90.1 23.62,90.1 | 22.35,90.1 IC8.3 22.35,89.98 21.08,89.98 | 23.62,90.1 IC8.2 | 23.62,90.1 IC8.7 | 28.28,94.76 C28.2 | C37.2 28.57,95.06 28.28,94.76 | 38.98,100.52 39.07,100.61 C24.2 | C36.1 40.25,99.25 38.98,100.52 | C25.2 37.55,98.27 35.81,100.01 35.81,100.9 33.14,103.57 33.14,103.95 31.87,105.22 31.49,105.22 29.08,107.63 | 38.98,100.52 40.38,99.12 40.63,99.12 41.91,97.85 44.32,97.85 44.83,98.36 44.83,105.85 v43.68,106.49 | 41.78,120.84 43.94,120.84 | SV3.6 10.41,123.38 8.5,121.47 8.5,111.06 v11.93,107.63 | 28.28,94.76 28.28,92.73 v27.81,92.26 | 21.08,89.98 21.08,86.29 v19.68,86.29 | 12.69,102.53 12.69,106.87 v11.93,107.63 | C32.2 53.12,123.25 43.94,123.25 | R91.1 41.78,123.95 41.78,120.84 | 47.37,81.86 47.37,81.85 | 47.37,81.86 | C31.2 48.29,82.78 47.37,81.86 | IC10.5 38.98,85.02 40,86.04 42.41,86.04 43.56,84.9 C34.- | C39.1 31.4,76.86 J2.1 | 39.87,107.5 40.13,107.5 41.03,108.41 C35.1 | C40.1 39.36,107.88 39.75,107.5 39.87,107.5 | C47.2 17.77,107.5 17.54,107.74 C48.1 12.17,107.74 12.06,107.63 v11.93,107.63 | Q19.3 6.13,100.66 8,102.53 12.69,102.53
  Bottom 0.61: S7.1 83.2,84.54 83.18,84.52 83.16,84.54 S7.2 | 83.26,119.11 83.31,119.06 | 83.26,119.11 S5.2 | 83.26,119.11 83.2,119.16 S5.1 89.94,119.16 99.31,109.79 99.31,96.71 97.91,95.31 92.58,95.31 92.2,95.69 | v43.68,106.49 43.94,106.87 45.46,108.39 45.46,110.68 | 45.46,110.68 45.46,113.35 46.35,114.23 46.35,116.27 45.08,117.54 41.78,117.54 v41.65,117.66 | 45.46,110.68 50.67,110.68 | v20.06,111.95 21.97,113.35 23.36,113.35 26.03,110.68 26.03,109.54 26.79,108.77 26.79,108.65 | 67.51,98.54 67.43,98.49 | 67.51,98.54 S8.2 | 67.41,101.66 67.41,98.64 67.51,98.54 | S8.1 67.41,101.66 | 71.62,100.39 70.35,101.66 67.41,101.66 | 65.27,89.6 LED6.K | 92.58,98.49 92.58,98.54 | U$5.GN 92.58,100.39 92.58,98.87 | 92.58,98.54 92.58,98.87 | 92.58,98.54 S6.1 | S6.2 92.58,105.04 92.58,98.87
  Bottom 0.813: 28.44,107.5 28.95,107.5 29.08,107.63 | 65.27,80.45 63.37,78.55 50.8,78.55 47.37,81.86 46.99,82.23 45.59,83.63 45.59,84.26 45.08,84.77 C34.- | 65.27,80.45 68.7,80.45 68.96,80.2 68.96,77.53 68.83,77.4 | 65.27,80.45 65.27,89.6 | 71.88,100.26 71.88,92.26 68.96,89.34 68.96,84.52 | 68.96,84.52 68.96,80.45 68.83,80.33 68.83,77.4 | 68.83,77.4 IC7.2 | 68.96,84.52 69.08,84.52 69.11,84.54 S7.1 83.28,84.54 83.31,84.52 84.96,84.52 87.24,86.8 87.24,90.74 92.2,95.69 92.58,96.07 92.58,98.49 92.6,98.51 S6.1 | U$5.S1 82.55,98.87 84.07,100.39 U$5.GN
  pour Bottom: 63.75,95.82 74.29,95.82 74.29,79.82 74.16,79.69 63.62,79.69 63.62,95.69
  pour Bottom: 24.89,111.69 33.4,111.69 33.4,103.44 24.89,103.44
  pour Bottom (isolate 0.813, rank 6, no thermals): -0.01,133.16 97.91,133.16 97.91,129.86 81.78,129.86 81.78,123.76 98.04,123.76 98.04,133.16 111.63,133.16 111.63,119.19 103.5,119.19 103.5,103.06 109.6,103.06 109.6,119.06 113.66,119.06 113.66,64.83 -0.01,64.83
  pour Top (isolate 0.813, rank 6, no thermals): -0.01,133.16 -0.01,64.83 113.66,64.83 113.66,133.16
1  (via drill 0.51, 3.2 pad 4)  (8 unrouted)
  Top 0.254: v2.79,55.94 2.53,57.08
  Bottom 0.254: 57.14,112.96 v54.6,112.96
  other vias: 2.66,130.24 59.56,121.98 100.2,121.98 59.56,81.47 3.17,3.62 3.04,8.95 110.74,68.77
+3V3  (via drill 0.6 pad 1.42)
  Top 0.406: C41.2 37.35,120.44 37.33,120.46 U$7.2V9 37.33,128.2 40.38,128.2 U$7.1V8 v40.38,121.6
  Bottom 0.203: 40.38,126.17 v40.38,121.6
  Bottom 0.254: 40.38,126.17 41.02,126.17 U$8.1
  Bottom 0.305: R90.2 41.02,129.41 41.02,126.17
  Bottom 0.406: U$8.1 43.05,126.17
+5V  (via drill 0.6 pad 1.27, 0.6 pad 1.42, 0.7 pad 1.42)  (2 unrouted)
  Top 0.254: 38.86,198.13 38.86,202.07
  Top 0.305: 53.72,206.32 53.72,204.74 51.94,204.74 51.94,204.72 | 51.94,204.72 51.94,204.61 | 51.94,204.72 IC5.4 | R54.1 55.75,191.27 | 53.72,206.32 53.65,206.32 v53.84,206.51 | IC5.6 52.01,206.32 52.06,206.26 52.12,206.32 53.72,206.32 | 33.9,202.07 33.86,202.11 | U$16.1 38.54,202.39 38.86,202.07 | 38.86,198.13 39.11,197.88 41.4,197.88 41.78,198.26 41.78,199.02 v42.16,199.4
  Top 0.406: R72.1 46.92,189.68 46.98,189.62 46.73,189.37 | 46.73,189.37 46.66,189.05 R53.1 43.36,189.05 43.36,189.18 | R71.1 46.92,189.18 46.73,189.37 | R5.1 54.54,199.46 54.86,199.78 55.75,199.78 56.13,199.4 56.19,199.46 R8.2 | 43.36,189.18 43.3,188.86 | 43.36,189.18 43.3,188.99 43.3,185.3 43.62,184.99 R14.2 43.62,185.12 43.56,185.18 43.68,185.3 v45.46,185.3 45.46,184.16 44.7,183.4 R9.2 | 55.75,191.27 55.62,191.27 | v45.59,125.03 45.59,118.04 44.7,117.16 | R93.2 18.47,115.7 18.54,115.63 18.6,115.7 R94.2 R95.2 | R95.2 20.88,115.7 20.95,115.63 | R95.2 22.79,115.7 22.85,115.63 22.92,115.7 R97.2 25.07,115.7 25.27,115.5 25.27,115.63 | 25.27,115.63 R96.2 25.46,115.7 25.52,115.63 25.65,115.63 | 25.27,115.63 25.14,115.5 | 20.82,114.11 20.95,114.23 | SV3.7 10.66,125.92 10.15,125.41 10.15,114.62 10.22,114.55 | C43.1 48.6,196.31 48.6,197.54 48.51,197.62 | v15.36,113.85 15.36,113.98 15.49,114.11 | 52.83,214.13 53.21,213.75 C14.1 52.84,212.04 52.95,212.1 | R35.2 52.97,211.78 52.95,212.1 | 52.95,212.1 52.83,212.23 51.43,212.23 v51.18,211.97 | 45.33,197.78 R11.2 45.01,198.07 44.76,198.32 | 52.7,197.62 48.51,197.62 | 41.78,199.72 U$9.1 | 52.7,193.18 53.33,193.18 55.56,190.95 | 55.56,190.95 55.62,190.89 | 55.56,190.95 R54.1 55.68,190.95 55.75,191.02 57.02,189.75 57.02,189.5 57.53,188.99 SV2.7 | 33.9,201.05 33.9,200.93 34.28,200.54 C45.1 34.28,200.67 33.9,201.05 | 33.9,201.05 33.9,202.07 33.9,202.2 v34.67,202.2 | 41.78,199.72 v42.16,199.4 | 33.86,202.11 C44.2 | 41.78,199.72 41.78,199.66 42.29,199.15 43.94,199.15 44.76,198.32 | 44.76,198.32 44.7,198.26 45.33,197.62 48.51,197.62 | Q7.2 26.47,187.65 27.22,188.4 27.22,189.62 v27.43,189.83
  Top 0.406: 43.34,190.42 43.38,190.49 v41.7,190.49 | R30.2 10.66,66.27 R28.2 12.63,66.4 13.84,67.6 13.84,70.8 14.09,71.05
  Top 0.61: 43.3,188.99 43.3,190.38 43.34,190.42 44.57,191.65 51.18,191.65 52.7,193.18 52.7,197.62 52.7,199.78 53.59,199.78 | 53.59,199.78 55.75,199.78 | 56.13,199.66 56.26,199.53 R8.2 | 44.57,114.11 44.57,114.23 44.7,114.36 v44.7,115.25 44.7,117.16 | 20.95,114.23 20.95,115.63 | v53.46,76.52 53.33,76.52 53.21,76.13 v53.21,68.01 53.08,67.88 44.32,67.88 43.68,67.24 39.62,67.24 38.98,67.88 16.63,67.88 16.63,71.05 14.09,71.05 12.57,71.05 | 45.33,88.83 v43.94,88.83 | 20.82,114.11 15.49,114.11 14.78,114.11 14.37,114.51 10.31,114.51 10.22,114.55 9.65,113.98 9.65,105.98 11.42,104.2 15.49,104.2 v16,103.69 | 53.59,199.78 R5.1 | 53.59,199.78 v53.59,201.05
  Top 0.813: 45.33,82.23 45.33,80.96 43.81,79.44 L3.1 | 45.33,82.23 45.33,88.83 45.33,114.11 44.57,114.11 20.82,114.11 | 53.33,76.52 v53.33,100.9 | 45.33,82.23 C34.+ | 39.49,215.28 49.14,215.28 51.18,213.24 v51.18,211.97 | 39.49,215.28 39.36,215.28 | L2.1 35.55,219.21 39.3,215.47 | 39.49,215.28 39.3,215.47 | 39.3,215.47 L1.1
  Bottom 0.305: C40.2 39.87,110.17 39.87,113.85 40.13,114.11 44.44,114.11 44.7,114.36 v44.7,115.25 44.57,115.38 R113.2 | R88.1 47.55,68.07 47.62,68.01 | 32.63,90.36 32.63,90.49 32.45,90.67 R85.1
  Bottom 0.406: C7.1 29.55,222.17 29.46,222.13 31.49,222.13 C10.+ | 48.07,182.44 R120.1 46.6,182.64 45.46,183.78 v45.46,185.3 | 23.32,106.74 23.49,106.74 | 23.32,106.74 IC9.27 | IC9.5 37.24,108.3 38.86,109.92 C40.2 | R84.1 77.65,68.01 77.59,68.01 | 47.49,68.01 47.49,68.13 47.55,68.13 R88.1 | 28.44,113.22 28.4,113.26 IC9.38 28.4,113.43 28.44,113.47 28.44,115.12 28.2,115.36 28.2,117.01 28.06,117.16 C38.2 28.19,117.16 27.81,117.54 27.81,117.66 25.65,117.66 25.01,118.3 18.28,118.3 17.65,117.66 14.09,117.66 13.46,117.03 10.66,117.03 10.15,116.52 10.15,114.87 10.66,114.36 14.85,114.36 v15.36,113.85 | R78.2 69.08,116.52 69.34,116.27 72,116.27 R77.1 73.27,117.79 70.23,120.84 62.86,120.84 58.29,116.27 58.29,108.9 56.7,107.32 54.04,107.32 53.08,106.36 53.08,105.47 53.27,105.28 R108.1 | v45.59,125.03 46.73,126.17 U$8.8 50.16,126.17 51.18,127.19 R112.2 | 48.38,84.65 C31.1 48.38,84.52 48,84.9 48,89.47 | IC9.17 29.2,99.5 28.81,99.11 C37.1 27.28,98.72 24.89,96.33 IC8.8 | IC8.8 24.89,94.68 | R83.1 19.11,96.52 19.04,96.58 18.28,96.58 18.03,96.33 18.03,92.64 | R117.1 27.93,90.23 | IC8.8 24.91,94.58 25.14,94.8 25.27,94.68 C28.1 26.58,94.59 26.16,94.17 26.03,94.17 26.03,90.49 | R117.1 27.93,90.1 | R116.1 R117.1 | R116.1 30.29,90.17 32.1,90.33 | 36.89,89.79 36.32,90.36 32.63,90.36 30.35,90.36 30.22,90.23 R116.1 | 36.95,89.79 36.95,89.72 36.89,89.66 R115.2 | 18.03,92.01 18.03,85.41 19.17,84.39 25.01,84.39 26.03,85.53 26.03,90.49 | 18.03,92.01 18.03,92.14 | 18.03,92.01 18.03,92.64 | 18.03,92.64 18.28,92.64 18.34,92.71 R82.1 | R117.1 27.75,90.17 27.43,90.49 26.03,90.49 | 30.73,68.01 30.86,67.88
  Bottom 0.406: IC10.8 42.54,81.21 43.81,79.94 44.83,79.94 45.13,79.64 D11.A 45.21,79.56 43.68,78.04 | C39.2 38.48,72.71 39.24,73.47 42.79,73.47 43.81,74.48 L3.1 | 43.81,84.9 43.56,84.64 | 48,89.47 44.57,89.47 v43.94,88.83 | 48,89.47 R81.1 | L3.1 43.81,76.64 | R110.2 41.97,77.59 42.41,78.04 43.68,78.04 | 43.68,78.04 43.68,76.64 L3.1 | 23.32,106.74 21.71,106.74 21.2,106.23 16.63,106.23 16.12,105.73 16.11,105.74 C48.2 15.98,105.74 16.12,105.6 | C20.2 48.85,204.32 49.14,204.61 53.21,204.61 53.84,205.24 | v34.67,202.2 36.19,202.2 38.6,199.78 41.78,199.78 v42.16,199.4 | v27.43,189.83 28.09,190.49 v41.7,190.49
  Bottom 0.61: R87.1 19.74,68.01 30.73,68.01 38.98,68.01 39.87,67.12 43.56,67.12 44.44,68.01 47.49,68.01 47.62,68.01 v53.21,68.01 68.83,68.01 69.72,67.12 73.78,67.12 74.67,68.01 77.59,68.01 96.51,68.01 97.4,67.12 101.72,67.12 102.61,68.01 105.28,68.01 105.28,69.66 105.21,69.66 R86.1 | 36.89,89.79 36.95,89.79 42.98,89.79 v43.94,88.83 | C48.2 15.89,105.74 16,105.85 v16,103.69 | C10.+ 31.74,222.01 34.79,225.06 L2.1
  Bottom 0.813: R108.1 53.27,101.47 v53.33,100.9 | L3.1 v53.46,76.52 | v51.18,211.97 53.84,209.31 v53.84,206.51 53.84,205.24 54.1,205.24 54.86,204.48 54.86,202.32 v53.59,201.05
+24V  (via drill 0.6 pad 1.42)  (4 unrouted)
  Top 0.406: v21.58,196.99 IC6.4 | C21.1 12.31,187.46 IC12.OUT
  Bottom 0.406: v21.58,196.99 21.58,194.96 17.65,191.02 C22.+ 15.11,191.02 14.35,190.26 14.35,187.59 13.33,186.57 IC12.OUT 13.58,186.7 15.72,186.7 16.86,185.56 21.2,185.56 22.09,186.45 28.95,186.45 29.84,185.56 29.84,178.19 30.86,177.18 38.98,177.18 41.78,174.38 J10.2
+_1  (via drill 5 pad 10.16)
  Top 3.81: v13.84,49.21 4.44,49.21 4.44,17.59 7.61,17.59
  Bottom 3.81: v13.84,49.21 4.44,49.21 4.44,17.59 7.49,17.59 7.49,17.71 ST5.1
+_2  (via drill 5 pad 10)
  Top 3.81: 41.91,49.34 31.62,49.34 31.62,17.71 ST7.1
  Bottom 3.81: ST7.1 31.62,17.71 31.62,49.21 v41.91,49.21 41.91,49.08
+_3  (via drill 5 pad 10)
  Top 3.81: 71.75,49.21 58.03,49.21 58.03,17.71 ST9.1
  Bottom 3.81: ST9.1 58.03,17.71 58.03,49.21 v71.62,49.21
+_4  (via drill 5 pad 10)
  Top 3.81: v99.69,49.08 109.34,49.08 109.34,17.71 ST11.1
  Bottom 3.81: v99.69,49.08 109.34,49.08 109.34,17.71 ST11.1
+_5
  Top 2.54: ST13.1 LSP1.MP
  Bottom 2.54: ST13.1 LSP1.MP
+_6
  Top 2.54: LSP4.MP ST15.1
  Bottom 2.54: LSP4.MP 124.63,205.85
+_7
  Top 2.54: LSP6.MP ST17.1
  Bottom 2.54: LSP6.MP ST17.1
+_8
  Top 2.54: LSP8.MP ST19.1
  Bottom 2.54: LSP8.MP ST19.1
+_9
  Top 2.54: 118.03,188.83 ST21.1 LSP10.MP
  Bottom 2.54: LSP10.MP 118.03,188.83
-5V  (via drill 0.6 pad 1.27)
  Top 0.406: C22.- 16.34,188.52 | C21.2 12.35,190.35 12.82,189.88 13.71,189.88 15.11,188.48 C22.- | D14.A 24.25,174.76 22.98,176.03 18.49,176.03 | 18.49,176.03 16.53,176.03 v15.74,176.82 | C22.- 18.77,188.48 19.65,187.59 | 19.65,187.59 19.65,181.85 18.49,180.68 18.49,176.03 | IC6.11 21.58,188.4 20.77,187.59 19.65,187.59
  Bottom 0.406: C53.- 14.62,178.09 15.74,176.97 v15.74,176.82
-_1  (via drill 5 pad 10)
  Top 0.254: 20.95,18.98 21.58,18.98 ST6.1
  Top 3.81: 13.84,22.03 20.95,22.03 20.95,18.98 ST6.1 20.95,17.46
  Bottom 3.81: 13.46,22.16 v13.84,22.16 20.95,22.16 ST6.1 20.95,17.46
-_2  (via drill 5 pad 10)
  Top 3.81: v41.91,22.16 48.89,22.16 ST8.1
  Bottom 3.81: v41.91,22.16 48.89,22.16 ST8.1
-_3  (via drill 5 pad 10)
  Top 3.81: v71.62,22.16 78.1,22.16 78.1,17.59
  Bottom 3.81: 78.1,17.59 ST10.1 78.1,22.16 v71.62,22.16
-_4  (via drill 1 pad 10)
  Top 3.81: v99.69,22.16 92.96,22.16 ST12.1
  Bottom 3.81: v99.69,22.16 92.96,22.16 ST12.1
-_5
  Top 2.54: ST14.1 LSP2.MP
  Bottom 2.54: ST14.1 LSP2.MP
-_6
  Top 2.54: LSP3.MP ST16.1
  Bottom 2.54: LSP3.MP 120.57,205.98
-_7
  Top 2.54: LSP5.MP ST18.1
  Bottom 2.54: LSP5.MP ST18.1
-_8
  Top 2.54: LSP7.MP ST20.1
  Bottom 2.54: LSP7.MP ST20.1
-_9
  Top 2.54: ST22.1 LSP9.MP
  Bottom 2.54: LSP9.MP 121.97,188.96
A
  Top 0.406: IC4.6 53.46,175.65 52.19,174.38 J7.3
A_S
  Bottom 0.406: R89.2 40.44,84.32 39.87,83.75 IC10.6 36.32,83.75 34.79,82.23 34.79,79.94 33.9,79.06 J2.2 33.9,75.5 34.67,74.74 40.89,74.74 41.91,75.75 R110.1
ADC6  (via drill 0.6 pad 1.27)
  Top 0.305: IC5.19 43.12,206.32 43.05,206.39 41.4,206.39 v41.14,206.64
  Top 0.406: R75.2 21.52,207.84 21.97,208.29 23.11,208.29 v23.36,208.04 23.43,207.97 R73.2
  Bottom 0.406: v23.36,208.04 23.74,208.42 27.43,208.42 28.82,209.82 28.82,210.32 30.09,211.59 33.78,211.59 34.28,211.09 34.28,205.88 35.74,204.42 | 35.74,204.42 35.81,204.35 | v41.14,206.64 41.91,206.64 43.05,205.5 43.05,201.56 42.03,200.54 39.49,200.54 35.68,204.35 35.74,204.42
ADC7  (via drill 0.6 pad 1.27)
  Top 0.254: 28.44,219.47 28.44,219.49 R76.2
  Top 0.305: v41.52,205.12 41.52,204.35 42.03,203.85 43.17,203.85 43.24,203.92 IC5.22
  Top 0.406: D6.3 28.44,216.04 28.38,216.36 28.38,217.31 | 28.38,217.31 R76.2 28.19,219.21 28.06,219.34 28.06,220.36 27.43,220.99 24.57,220.99 R74.1 | 28.44,219.47 28.38,219.4 | 43.05,203.85 43.12,203.92 IC5.22 | v29.33,217.31 28.38,217.31
  Bottom 0.406: v29.33,217.31 29.33,215.15 29.71,214.77 34.03,214.77 36.82,211.97 36.82,208.04 39.75,205.12 v41.52,205.12
AVCC  (via drill 0.6 pad 1.27)
  Top 0.305: 43.3,207.15 IC5.18 43.33,207.05 43.3,207.02 43.17,207.15 42.29,207.15 42.03,207.4 v42.03,209.56
  Top 0.406: R18.2 36.63,211.91 36.7,212.1 v38.09,212.1
  Bottom 0.305: 37.97,212.23 39.87,212.23 40.76,211.34 40.76,210.58 v42.03,209.56
  Bottom 0.406: v38.09,212.1 37.97,212.23 36.82,213.37 36.82,215.4 36.8,215.4 34.89,217.31 35.05,217.46 C17.2 | C17.2 35.3,217.05 | C16.+ 33.14,216.52 33.62,217 34.54,217 35,217.46 C17.2
B
  Top 0.406: J7.2 IC4.7
B_S
  Top 0.406: R114.2 41.31,75.54 40,74.61 37.71,74.61 36.44,75.88 J2.3 36.44,77.02
  Bottom 0.406: J2.3 36.44,81.85 37.08,82.48 IC10.7 40.25,82.48 40.31,82.42 R89.1
CS1
  Top 0.305: IC5.14 46.42,212.03 46.1,212.36 41.4,212.36 40.89,211.85 40.89,207.91 39.62,206.64 U$16.2
  Top 0.406: U$16.2 38.48,206.64
CS2
  Top 0.305: U$9.2 39.49,201.05 39.75,201.31 42.54,201.31 42.79,201.56 44.06,201.56 44.95,202.45 45.97,202.45 46.35,202.07 46.35,201.05 46.48,200.93 46.42,200.87 IC5.27
CS_LCD  (via drill 0.6 pad 1.42)
  Top 0.406: R105.2 v20.82,119.82 R95.1
  Bottom 0.406: v20.82,119.82 20.82,120.2 22.6,121.98 32.38,121.98 34.16,120.2 34.16,115.12 33.17,114.13 33.17,113.47 33.2,113.44 IC9.44
E_A
  Bottom 0.406: R79.1 70.54,115.19 70.86,114.87 72.64,114.87 72.77,115 R77.2 73.34,115.19 73.72,114.55 75.31,112.96 81.4,112.96 82.55,111.82 82.55,111.19 | 82.55,111.19 U$5.A.A | 82.55,111.19 U$5.A
E_B
  Bottom 0.406: R78.1 67.18,115.12 67.81,115.12 68.57,114.36 68.57,113.73 69.46,112.84 71.88,112.84 72.51,112.2 72.51,110.42 73.53,109.41 76.19,109.41 77.97,111.19 U$5.B U$5.B.B | R78.1 68.32,115.25 68.19,115.12 67.75,114.81 | R78.1 67.81,115 67.68,114.87 R80.1
EN_A
  Bottom 0.406: IC9.11 35.62,103.5 36.32,102.8 36.32,101.66 37.33,100.65 C24.1 37.37,99.72 38.09,98.99 38.86,98.99 39.62,98.23 39.62,95.95 40.76,94.8 41.27,94.8
  Bottom 0.61: R79.2 70.61,118.68 69.72,119.57 63.62,119.57 62.86,118.81 62.86,118.55 59.68,115.38 59.68,104.96 53.84,99.12 52.06,99.12 47.75,94.8 41.27,94.8
EN_B
  Bottom 0.406: IC9.12 33.2,101.6 34.54,100.26 34.54,97.98 | 34.54,97.98 34.54,96.71 35.81,95.44 35.81,94.3 36.44,93.66 37.46,93.66 | C25.1 35.81,97.6 35.43,97.98 34.54,97.98
  Bottom 0.61: 37.46,93.66 48.25,93.66 52.45,97.85 54.35,97.85 61.08,104.58 61.08,114.62 64.26,117.79 65.27,117.79 65.4,117.67 R80.2
ERROR_ZAS  (via drill 0.7 pad 1.42)
  Top 0.406: v27.81,119.82 27.81,125.92 v27.93,126.05
  Bottom 0.406: 46.6,131.63 33.52,131.63 v27.93,126.05 | 46.6,131.63 46.6,129.98 U$8.5 | 31.62,113.32 IC9.42 31.6,113.33 31.62,113.35 31.62,114.87 32.51,115.76 32.51,119.31 32,119.82 v27.81,119.82 | R112.1 51.11,130.17 49.78,131.51 46.73,131.51 46.6,131.63
GND  (via drill 0.6 pad 1.27, 0.6 pad 1.42, 0.6 pad 1.68, 0.6 pad 1.78)  (5 unrouted)
  Top 0.254: R33.1 37.33,190.64 37.53,190.83
  Top 0.305: 51.81,205.5 51.81,205.52 IC5.5 | 31.2,203.81 30.6,203.21 30.6,200.93 30.98,200.54 32.25,200.54 34.03,198.77 | C44.1 34.5,203.81 34.92,204.23 34.92,206.01 34.28,206.64 U$16.7
  Top 0.406: TRAN3.3 60.93,185.71 60.83,185.69 60.83,191.53 SV2.6 58.16,191.53 56.89,192.8 56.89,193.31 55.11,195.08 LED1.K | Q8.2 25.33,181.94 24.89,182.38 24.89,183.4 24.51,183.78 | 24.51,183.78 R1.2 | 24.51,183.78 23.24,183.78 v23.11,183.65 | C43.2 50.67,196.23 50.5,196.06 C2.2 | 50.16,193.81 50.41,194.07 50.41,193.18 49.91,192.67 45.21,192.67 44.83,193.05 | U$9.7 39.49,195.97 39.75,196.23 41.52,196.23 41.91,195.85 41.91,191.78 | 50.41,204.74 50.41,203.97 51.94,203.97 51.94,203.92 IC5.3 | 49.02,204.72 50.41,204.72 50.41,204.74 | 49.02,204.72 IC5.21 | 49.02,204.72 v49.02,205.88 | U$16.7 31.87,206.64 31.49,207.02 31.49,210.96 31.43,211.02 | 37.53,190.83 T5.2 | 37.53,190.83 37.59,190.89 | 31.36,211.09 31.43,211.02 | 31.43,211.02 31.36,210.96 | R76.1 26.48,217.37 26.16,217.05 26.22,216.99 D6.1 26.35,216.99 26.41,216.93 24.25,216.93 23.87,216.55 23.87,215.91 23.8,215.85 R12.2 23.8,213.95 24.25,213.5 24.12,213.37 R3.1 23.93,213.31 24,213.24 | R75.1 19.62,207.85 19.68,207.91 v19.68,210.07 | 37.53,190.83 37.53,191.59 37.46,191.65 37.46,191.78 35.3,191.78 35.17,191.91 R61.1 34.86,191.97 34.79,191.91 34.03,192.67 R70.1 32.95,192.6 30.98,190.64 31.15,190.47 C18.2 | 50.41,205.5 50.41,207.91 51.68,209.18 54.86,209.18 56.26,207.78 J9.3 | 50.41,205.5 50.41,204.74 | C14.2 54.49,213.84 54.91,214.26 58.16,214.26 58.29,214.13 | 50.41,205.5 51.81,205.5 | C44.1 31.2,203.81 | 34.03,198.77 34.07,198.81 C45.2 | R42.1 20.82,202.7 20.95,202.83 21.71,202.83 | R69.1 22.79,202.51 22.47,202.83 21.71,202.83 | 21.71,202.83 21.71,203.97 v21.84,204.1 | 12.38,195.4 12.57,195.21 13.96,195.21 R45.2 | C49.1 12.19,195.21 12.38,195.4
  Top 0.406: R22.2 33.33,181.18 33.78,180.73 33.78,179.59 34.92,178.45 34.92,174.38 35.43,173.87 35.43,167.91 v35.55,167.65 | 44.83,193.05 44.7,193.18 | VR1.A 44.83,193.05 | J10.8 26.54,172.1 26.79,172.35 D15.C | R119.1 11.68,196.1 12.38,195.4
  Top 0.61: J9.1 58.16,212.86 | J9.1 59.68,212.86 60.57,211.97 60.57,208.55 59.81,207.78 J9.3 | J9.1 58.29,212.74 | v59.81,216.67 58.29,216.67 58.29,214.13 J9.1 | R3.1 23.93,213.43 24,213.5 24.25,213.5 | VR1.A 43.68,193.05 42.41,191.78 41.91,191.78 37.46,191.78 | 32.89,193.05 32.95,193.11 R70.1 | 24.57,211.53 R66.2 | 24.57,211.53 22.98,209.94 19.81,209.94 v19.68,210.07 | 24.57,211.53 24.82,211.53 25.14,211.85 25.14,213.5
  Top 0.813: 31.36,211.09 31.36,213.5 31.24,213.5 | 31.24,213.5 25.14,213.5 24.25,213.5 | 31.24,213.5 31.24,213.37 31.74,213.88 v31.74,217.05
  Top 1.27: IC3.GND 34.06,229.12 38.35,224.83 38.35,220.61 40.69,218.27 43.02,218.27 v43.02,218.32
  Top 1.778: v59.81,216.67 51.18,216.67 49.52,218.32 v43.02,218.32
  Bottom 0.305: C15.1 48.64,207.66 48.13,207.15 48.13,207.02 | 35.55,165.02 35.55,165.11 v35.55,167.65
  Bottom 0.406: C6.2 62.99,221.88 62.86,221.75 | 15.7,183.69 16.38,183.02 16.38,181.11 15.87,180.61 C53.+ | 15.7,183.69 15.23,184.16 IC12.GND | v23.11,183.65 21.2,183.65 20.7,184.16 16.17,184.16 15.7,183.69 | C7.2 29.55,223.87 29.33,224.29 29.33,225.44 | 27.55,225.44 27.55,225.31 27.43,225.18 | C15.1 48.6,207.49 48.89,207.49 48.89,208.04 | 48.13,207.02 48.13,205.88 48.25,205.88 | 62.86,197.88 63.11,197.88 | v49.02,205.88 48.25,205.88 | C17.1 36.82,217.22 36.82,219.72 | C46.- 19.68,211.09 v19.68,210.07 | C20.1 47.15,204.77 48.25,205.88 | v21.84,204.1 21.71,204.23 | R7.2 32.13,220.23 33.52,218.83 | 37.46,223.56 37.59,223.56 37.68,223.65 C8.2 | C11.1 59.41,228.87 59.84,229.3 62.86,229.3 62.94,229.3
  Bottom 0.61: 26.66,165.11 26.66,164.98 26.54,165.11 | LED1.K 56.89,195.59 57.14,195.34 62.86,195.34 | C20.1 47.11,204.1 44.95,201.94 44.95,200.04 44.57,199.66 44.57,198.39 44.95,198 VR1.A | v21.84,204.1 21.84,207.91 v19.68,210.07 | 21.71,204.23 19.55,204.23 18.66,203.34 18.66,198.13 16.63,196.1 R119.1
  Bottom 0.813: Q1.S 25.39,224.93 25.9,225.44 27.55,225.44 29.33,225.44 31.62,225.44 | 31.62,225.44 C10.- | 31.62,225.44 32.89,225.44 34.16,226.71 36.06,226.71 37.46,225.31 37.46,223.56 37.46,219.72 37.48,219.7 37.48,219.72 36.82,219.72 | 36.82,219.72 34.41,219.72 33.52,218.83 v31.74,217.05 | v31.74,217.05 C16.- v31.74,217.05 | 26.66,165.11 26.66,165.24 26.54,165.37 26.54,172.1 | 43.02,219.75 42.97,219.75 42.95,219.72 36.82,219.72
  Bottom 1.27: X3.4 22.52,172.17 20.19,174.51 D7.A 15.36,174.51 12.19,177.68 12.19,179.72 13.08,180.61 C53.+
  Bottom 1.778: C9.- 42.79,220.89 42.77,220.86 43.02,220.61 43.02,219.75 v43.02,218.32
  Bottom 2.184: 62.86,216.67 62.86,197.88 62.86,195.34 62.86,173.11 56.76,168.03 38.6,168.03 38.6,164.98 35.55,165.02 26.66,165.11 26.54,165.11 22.6,165.11 22.47,164.98 22.52,164.93 X3.3 22.52,165.06 22.47,165.11 22.52,165.16 X3.4 22.52,167.45 22.47,167.4 17.52,167.4 | 62.86,216.67 62.86,221.75 62.86,229.3 62.86,230.9 60.7,233.06 B1.- | 17.52,164.73 X3.1 17.52,167.4 | 17.52,167.4 X3.2 | 62.86,216.67 v59.81,216.67
  pour Bottom (isolate 0.406): 0.12,235.47 64.64,235.6 64.64,161.17 56.64,161.17 56.64,167.02 40.76,167.02 40.76,161.3 0.12,161.17
  pour Top (isolate 0.406): 44.06,208.54 51.05,208.54 51.05,201.56 44.06,201.56
GND_M
  Top 0.406: R17.2 R16.2 | R16.2 54.54,57.25 54.6,57.19 | R16.2 54.54,56.1 52.57,54.14 52.57,41.69 54.6,39.66 J8.8
  Top 0.61: J8.8 54.6,33.69 53.46,32.55 53.46,15.02 50.29,11.85 45.21,11.85 43.17,9.82 LED12_POWER3.K
GND_M1
  Top 0.406: R20.2 R19.2 | R19.2 26.85,57.12 26.79,57.06 | R19.2 26.85,56.1 23.49,52.74 23.49,42.84 26.54,39.79 26.54,38.01 26.66,37.88 26.56,37.78 J6.8
  Top 0.61: J6.8 26.54,35.09 25.52,34.07 25.52,13.63 20.95,9.05 15.23,9.05 LED12_POWER2.K
GND_M2
  Top 0.406: 111.18,56.36 111.05,56.49 R23.2 | 111.18,56.36 R21.2 111.18,56.49 110.99,56.3 110.99,55.79 109.98,54.77 96.26,54.77 93.85,52.36 93.85,44.74 96.13,42.45 103.63,42.45 104.77,41.31 J3.8 | 111.18,56.36 111.37,56.17
  Top 0.61: J3.8 104.77,34.45 103.75,33.44 103.75,30.77 101.72,28.74 93.21,28.74 89.28,24.8 89.28,16.04 92.45,12.86 99.94,12.86 100.96,11.85 LED12_POWER1.K
GND_M3
  Top 0.406: R25.2 84,57.63 83.94,57.57 R24.2 84,55.72 81.28,53 81.28,44.23 79.24,42.2 J4.8 79.24,37.5
  Top 0.61: 79.24,37.5 79.24,28.1 82.42,24.93 82.42,14.13 79.88,11.59 74.67,11.59 73.15,10.07 73.15,9.18 73.27,9.05 73.17,8.95 LED12_POWER.K
GND_RS485  (via drill 0.6 pad 1.42)
  Top 0.406: 47.01,178.47 47.01,178.22 | 47.01,178.47 46.98,178.45 46.98,177.81 46.48,177.3 46.48,174.13 47.49,173.11 49.65,173.11 | 47.01,178.47 TRAN1.3 | IC4.5 52.19,176.03 50.67,174.51 50.29,174.51 49.65,173.87 49.65,173.11 | v59.3,174.51 59.3,174.38 60.04,173.65 C13.1 60.41,172.39 61.59,171.21 61.59,169.81 61.08,169.3 50.29,169.3 49.65,169.94 49.65,171.97 | 49.65,171.97 J7.4 | 49.65,171.97 49.65,173.11
  Bottom 0.305: 59.36,179.4 58.29,178.32 56.64,178.32 55.98,177.66
  Bottom 0.406: 59.36,179.4 T2.2 | 55.98,177.66 TRAN2.3 55.98,176.44 56.51,175.91 57.91,175.91 v59.3,174.51
IOUT
  Top 0.406: U$9.8 40.76,193.18 40.38,192.8 36.57,192.8 35.43,193.94 35.36,193.87 R61.2 35.17,193.81 33.52,195.46 31.24,195.46 29.46,197.24 27.55,197.24 27.3,196.99 23.87,196.99 22.85,195.97 IC6.12
K1
  Top 0.61: S8.4 62.88,92.11 65.91,89.09 76.96,89.09 76.93,89.06 S7.4 | S5.3 69.23,114.64 62.99,108.39 62.99,105.09 62.94,105.04 S8.3
  Bottom 0.305: IC9.15 30.8,100.06 30.98,99.88 30.98,97.6 32.38,96.2 32.89,96.2 34.03,95.06 34.03,93.91 34.28,93.66 | 34.28,93.66 R85.2 | 34.79,92.26 34.79,93.15 34.28,93.66
  Bottom 0.61: 83.28,114.64 S5.4 | 83.28,114.64 S5.3 79.98,114.64 80,114.62 | 83.28,114.64 83.31,114.62 90.16,114.62 97.15,107.63 97.15,105.09 97.12,105.07 S6.4 97.12,98.64 97.15,98.61 97.12,98.59 S6.3 | 34.79,92.26 48.64,92.26 52.83,96.45 54.73,96.45 59.81,101.53 62.99,101.53 | S8.4 63.14,98.59 62.99,98.61 62.99,101.53 | S8.3 63.16,105.04 63.24,104.96 62.99,104.71 62.99,101.53
  Bottom 0.813: U$5.S2 77.47,89.72 76.81,89.06 S7.4 76.93,89.06 76.96,89.09 76.98,89.06 S7.3
KIERUNEK_RS485  (via drill 0.5 pad 1.42, 0.7 pad 1.42)
  Top 0.406: v35.05,89.09 34.54,89.6 34.54,95.18 33.65,95.18 29.08,99.76 19.55,99.76 18.16,101.15 18.16,104.58 v18.66,105.09
  Bottom 0.406: IC10.2 32.48,82.59 32.51,82.61 32.48,82.64 IC10.3 34.16,83.75 34.99,84.58 R115.1 35.05,87.31 v35.05,89.09 | IC9.25 23.38,105.1 23.36,105.09 v18.66,105.09
LDAC  (via drill 0.6 pad 1.27)
  Top 0.305: 45.62,199.75 IC5.26
  Top 0.406: U$9.5 36.95,195.59 36.7,195.85 35.17,195.85 v34.67,196.35 | v32.89,210.45 32.89,209.18 U$16.5 | v46.1,199.27 45.62,199.75
  Bottom 0.406: v32.89,210.45 33.27,210.07 33.27,201.81 34.67,200.42 v34.67,196.35 34.67,195.08 38.22,191.53 46.35,191.53 47.37,192.54 47.37,195.97 46.1,197.24 v46.1,199.27
LED1
  Bottom 0.406: U$13.K 98.42,69.02 97.66,69.78 80.64,69.78 | 80.64,69.78 80.51,69.78 | IC9.21 26,100.75 25.27,100.01 19.04,100.01 17.14,98.11 17.14,73.98 17.77,73.34 21.71,73.34 23.62,71.44 38.73,71.44 39.62,72.32 49.14,72.32 50.54,70.93 74.16,70.93 74.8,71.56 78.86,71.56 80.64,69.78
LED2
  Bottom 0.406: IC9.22 25.2,101.09 24.89,100.77 18.66,100.77 16.38,98.49 16.38,73.59 17.39,72.58 21.2,72.58 23.11,70.67 39.36,70.67 40.13,71.44 48.64,71.44 50.03,70.04 69.97,70.04 70.48,69.53 U$11.K
LED3
  Bottom 0.406: IC9.23 20.63,103.5 19.3,102.17 18.92,102.17 15.62,98.87 15.62,73.09 16.89,71.82 20.7,71.82 22.6,69.91 39.49,69.91 U$15.K
LED4
  Bottom 0.406: 13.46,72.83 12.57,71.94 U$14.K | 13.46,72.83 13.71,73.09 | IC9.24 20.29,104.3 18.92,102.93 18.54,102.93 14.85,99.25 14.85,74.23 13.46,72.83
MISO  (via drill 0.6 pad 1.27)
  Top 0.305: IC5.16 | v43.68,211.21 43.68,210.7 44.83,209.56
  Top 0.406: 44.83,209.56 44.82,209.56 IC5.16
  Bottom 0.406: v43.68,211.21 43.68,214.01 55.88,214.01 55.88,206.26 56.76,205.37 56.76,203.72 SV2.2
MISO_G  (via drill 0.6 pad 1.42)
  Top 0.406: SV3.2 14.09,113.22 14.98,112.33 18.54,112.33 19.3,113.09 22.85,113.09 23.62,112.33 36.32,112.33 v36.32,112.71
  Bottom 0.406: v36.32,112.71 36.32,111.06 35.94,110.68 35.05,110.68 34.95,110.7 | 34.95,110.7 34.92,110.68 | 34.95,110.7 IC9.2
MOSI  (via drill 0.6 pad 1.27)
  Top 0.305: 45.21,211.47 v45.33,211.21 45.62,211.21 IC5.15
  Top 0.406: 27.3,180.35 27.3,183.02 26.54,183.78 R1.1 26.73,183.84 26.79,183.91 26.79,184.42 25.46,185.75 Q7.1 | 27.3,180.35 27.05,180.1 26.16,180.1 26.1,180.04 Q8.1 | SV2.3 62.23,195.72 62.23,172.35 62.73,171.84 62.73,169.68 61.46,168.41 56.89,168.41 54.73,166.25 54.73,166.13 31.87,166.13 30.35,167.65 30.35,173.62 28.44,175.53 28.44,179.21 27.3,180.35
  Bottom 0.254: 58.29,199.15 58.92,199.53 SV2.3
  Bottom 0.406: v45.33,211.21 45.33,213.24 54.99,213.24 54.99,206.01 56,204.99 56,201.43 58.29,199.15
MOSI_G  (via drill 0.6 pad 1.42)
  Top 0.406: R93.1 16.5,117.54 | R93.1 v16.5,119.7 R107.2 | SV3.3 13.58,115.76 15.36,117.54 16.38,117.54 16.44,117.6 R93.1
  Bottom 0.406: IC9.1 34.73,111.5 35.05,111.57 35.05,120.58 32.89,122.87 17.65,122.87 16.5,121.73 v16.5,119.7
N$1  (via drill 0.6 pad 1.27)
  Top 0.406: 22.6,206.13 22.28,205.81 R39.1 22.35,205.75 v24.12,204.35
  Bottom 0.406: v24.12,204.35 24.51,203.97 26.79,203.97 26.92,203.85 27.81,203.85 29.08,202.58 29.08,200.29 28.95,200.16 CA6V.A
N$2  (via drill 0.6 pad 1.27)
  Top 0.406: IC6.6 19.04,200.8 18.66,201.18 16.63,201.18 15.93,200.48 R34.1 | R34.1 15.87,200.42 | 16.89,208.29 17.01,208.16 R36.2 15.8,208.23 v14.98,207.4 | R34.1 15.87,200.54 15.49,200.93 | R34.1 15.81,200.48 15.49,200.8 v15.49,202.07
  Bottom 0.406: v14.98,207.4 14.98,202.58 v15.49,202.07
N$3
  Top 0.406: IC6.2 24.12,197.88 24.25,197.75 26.16,197.75 26.54,198.13 26.92,198.13 | CA6V.S 31.36,197.62 30.86,198.13 26.92,198.13 | C42.2 27.05,198.26 26.92,198.13
N$4
  Top 0.406: IC6.5 20.31,200.8 18.48,202.64 R42.2 18.79,202.7 | 18.79,202.7 18.92,202.58 | R32.1 18.6,202.9 18.79,202.7
N$5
